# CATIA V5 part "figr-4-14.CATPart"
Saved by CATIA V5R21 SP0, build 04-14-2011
Part number: Part1
Bounding box of the stored display mesh (mm): x -69.981 to 69.981, y -240 to 0, z -69.908 to 69.908
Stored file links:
  D:\CATIA V5R21 E-RESOURCES\CATIA-V5R21\catia-v5r21-prt\c04-catia-v5r20-prt\catia-v5r21-figr-4-14.CATPart
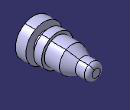
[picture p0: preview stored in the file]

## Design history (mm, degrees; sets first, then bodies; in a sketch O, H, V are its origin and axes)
Body1 (main body)
  Sketch1 on yz-plane, origin (0, 0, 0), H (0, 1, 0), V (0, 0, 1)
    line L1 (0, 0) -> (0, 15.359)
    arc A1 centre (-15.359, 15.359) radius 15.359 from (0, 15.359) to (-15.359, 30.718) ccw
    point P2 (-15.359, 15.359)
    line L2 (-15.359, 30.718) -> (-49.6877, 30.718)
    line L3 (-49.6877, 30.718) -> (-91.8922, 49.6007)
    line L4 (-91.8922, 49.6007) -> (-149.3038, 49.6007)
    line L5 (-149.3038, 49.6007) -> (-149.3038, 60)
    line L6 (-149.3038, 60) -> (-180, 60)
    line L7 (-180, 60) -> (-180, 38.9967)
    line L8 (-180, 38.9967) -> (-200, 40)
    line L9 (-200, 40) -> (-200, 70)
    line L10 (-200, 70) -> (-240, 70)
    line L11 (-240, 70) -> (-240, 0)
    line L12 (-240, 0) -> (0, 0)
    axis line L13 (-300, 0) -> (50, 0)
    vertical: L1 V, L5 V, L7 V, L9 V, L11 V
    tangency: A1 L1, L2 A1, L8 A1, L12 A1, L13 A1
    coincidence: L3 P2
    horizontal: L4 H, L6 H, L10 H, L2 H
    fix: L12
  Shaft1: profile Sketch1, axis Sketch1.H, angle 360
